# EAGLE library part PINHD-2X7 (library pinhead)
PIN HEADER
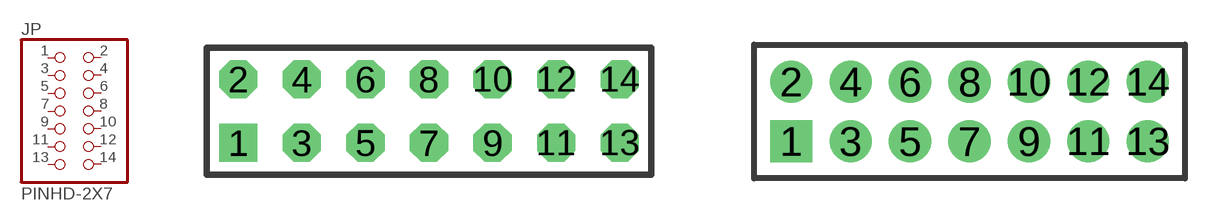
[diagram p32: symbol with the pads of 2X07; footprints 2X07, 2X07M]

Designator prefix JP

## PINHD-2X7  [2X07]
1  1  pas
2  2  pas
3  3  pas
4  4  pas
5  5  pas
6  6  pas
7  7  pas
8  8  pas
9  9  pas
10  10  pas
11  11  pas
12  12  pas
13  13  pas
14  14  pas

## PINHD-2X7M  [2X07M]
Pads as for 2X07

## Footprint 2X07 (pad centres in mm)
PIN HEADER - 0.1"
drill 1.016 square: 1 -7.62,-1.27
drill 1.016 octagon: 2 -7.62,1.27; 3 -5.08,-1.27; 4 -5.08,1.27; 5 -2.54,-1.27; 6 -2.54,1.27; 7 0,-1.27; 8 0,1.27; 9 2.54,-1.27; 10 2.54,1.27; 11 5.08,-1.27; 12 5.08,1.27; 13 7.62,-1.27; 14 7.62,1.27

## Footprint 2X07M (pad centres in mm)
PIN HEADER - 2MM"
drill 0.914 square: 1 -6,-1
drill 0.914 round: 2 -6,1; 3 -4,-1; 4 -4,1; 5 -2,-1; 6 -2,1; 7 0,-1; 8 0,1; 9 2,-1; 10 2,1; 11 4,-1; 12 4,1; 13 6,-1; 14 6,1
